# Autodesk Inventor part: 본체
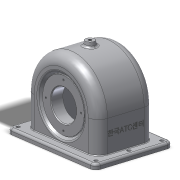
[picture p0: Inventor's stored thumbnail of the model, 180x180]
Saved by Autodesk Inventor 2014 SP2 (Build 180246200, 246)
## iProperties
Created: 2015-09
Part Number: 본체
Material: 알루미늄 6061
Document SubType Name: Modeling
Designer: 201-20
Density: 2.71 g/cm^3
Appearance: 알루미늄 - 평지
Mass: 723.189 g
Surface Area: 889.819 cm^2
Volume: 266.859 cm^3
Author: 201-20
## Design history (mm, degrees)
sketch "스케치6"
  geometry: L1 (-70, -40)-(70, -40); L2 (70, -40)-(70, -47); L3 (70, -47)-(-70, -47); L4 (-70, -47)-(-70, -40); 2 further points
  constraints: 8 end point, 2 parallel, 1 horizontal, 1 midpoint, 1 perpendicular, 1 vertical alignment
  dimensions: "d2" = 140 distance of L2.end L3.end; "d3" = 7 distance between parallel lines of L1 L3; "d4" = 47 distance from line of L3 point (0, 0)
extrude "돌출2" new body sketch "스케치6" stored distance "d5" = 104; taper "d6" = 0 deg
sketch "스케치10"
  geometry: L1 (70, -40)-(-70, -40) reference; L2 (-57, 0)-(57, 0); L3 (57, 0)-(57, -40); L4 (-57, -40)-(-57, 0); L5 (70, -47)-(-70, -47) reference; L6 (-51, 0)-(-51, -40); L7 (51, 0)-(51, -40); L8 (57, -40)-(51, -40); L9 (-51, -40)-(-57, -40); L10 (-51, -40)-(51, -40); A1 r 57 centre (0, 0) between (57, 0) and (-57, 0); A2 r 51 centre (0, 0) between (51, 0) and (-51, 0); 2 further points
  constraints: 16 end point, 5 perpendicular, 4 parallel, 4 point on circle, 3 midpoint, 2 centre point, 2 tangent, 1 coincident, 1 horizontal, 1 point on line, 1 vertical alignment
  dimensions: "d20" = 47 distance between parallel lines of L2 L5; "d21" = 6 radial gap between concentric circles of A1 A2; "d110" = 51 radius of A2
extrude "돌출3" join sketch "스케치10" stored distance "d17" = 77; taper "d18" = 0 deg
extrude "돌출4" cut sketch "스케치10" stored distance "d22" = 67; taper "d23" = 0 deg
sketch "스케치14"
  geometry: L1 (19, -18.5)-(121, -18.5); L2 (121, -18.5)-(121, -85.5); L3 (121, -85.5)-(19, -85.5); L4 (19, -85.5)-(19, -18.5); 3 further points
  constraints: 8 end point, 2 midpoint, 2 parallel, 1 horizontal, 1 horizontal alignment, 1 perpendicular, 1 vertical alignment
  dimensions: "d24" = 67 distance of L1.end L2.end; "d25" = 102 distance of L1.start L1.end
extrude "돌출5" cut sketch "스케치14" distance "d26" = 20; taper "d27" = 0 deg
fillet "모깎기1" dims "d28" = 14
fillet "모깎기3" dims "d34" = 9
sketch "스케치15"
  geometry: L1 (57, 38.5)-(0, 38.5) reference; L2 (51, 33.5)-(0, 33.5) reference; L3 (39.747, 33.5)-(28, 19.5); L4 (28, 19.5)-(20, 19.5); L5 (20, 19.5)-(20, 35.5); L6 (33, 33.237)-(37.416, 38.5); L7 (33, 33.237)-(33, 35.5); L8 (33, 35.5)-(20, 35.5); L9 (37.416, 38.5)-(39.747, 33.5); L10 (37.416, 38.5)-(20, 38.5); L11 (20, 38.5)-(20, 35.5); L12 (0, -72.8)-(0, 72.8) reference; 1 further point
  constraints: 18 end point, 3 parallel, 3 perpendicular, 3 point on line
  dimensions: "d30" = 28 horizontal distance of L3.end point (0, 0); "d31" = 3 distance between parallel lines of L8 L1; "d32" = 16 distance of L4.end L5.end; "d33" = 50 deg angle of L4 L3; "d35" = 33 distance from line of L7 point (0, 0); "d37" = 5 distance between parallel lines of L3 L6; "d38" = 20 distance from line of L5 point (0, 0)
revolve "회전1" stored, may be unused: angle "d39" = 90 deg
revolve "회전2" stored, may be unused: angle "d40" = 90 deg
sketch "스케치17"
  geometry: C1 r 31 at (0, 0); C2 r 20 at (0, 0); 1 further point
  constraints: 2 centre point, 2 coincident
  dimensions: "d41" = 62 diameter of C1; "d42" = 40 diameter of C2
extrude "돌출6" join sketch "스케치17" distance "d43" = 10; taper "d44" = 0 deg
sketch "스케치18"
  geometry: C1 r 20 at (0, 0) reference; 1 further point
extrude "돌출7" cut sketch "스케치18" distance "d45" = 87; taper "d46" = 0 deg
node "작업 평면2"
sketch "스케치20"
  geometry: C1 r 6 at (70, -52); 1 further point
  constraints: 1 centre point, 1 coincident
  dimensions: "d48" = 12 diameter of C1
extrude "돌출8" join sketch "스케치20" stored distance "d49" = 7; taper "d50" = 10 deg
hole "구멍1" diameter "d53" = 4.459; stored, may be unused: countersink angle "d57" = 90 deg, drill point angle "d59" = 0 deg; dims "d54" = 30, "d55" = 4, "d56" = 2, "d58" = 30, "d60" = 10, "d61" = 10
fillet "모깎기4" dims "d62" = 7
sketch "스케치21"
  geometry: 2 further points
  dimensions: "d63" = 62 horizontal distance of point (1, 8) point (63, 52); "d64" = 44 vertical distance of point (1, 8) point (63, 52)
hole "구멍2" sketch "스케치21" at (1, 8) diameter "d65" = 5; stored, may be unused: countersink angle "d69" = 90 deg, drill point angle "d71" = 0 deg; dims "d66" = 10, "d67" = 4, "d68" = 2, "d70" = 10
fillet "모깎기5" dims "d75" = 3, "d76" = 3, "d77" = 3, "d78" = 1
sketch "스케치22"
  geometry: 2 further points
  constraints: 1 vertical alignment
  dimensions: "d79" = 28 distance of point (0, 28) point (0, 0)
hole "구멍3" sketch "스케치22" at (0, 28) diameter "d80" = 2.459; stored, may be unused: countersink angle "d84" = 90 deg, drill point angle "d86" = 118 deg; dims "d81" = 7, "d82" = 4, "d83" = 2, "d85" = 9
chamfer "모따기1" distance "d90" = 1; stored, may be unused: second distance "d91" = 2, angle "d92" = 45 deg
fillet "모깎기6" dims "d93" = 0.5
sketch "스케치23"
  geometry: 2 further points
  constraints: 1 vertical alignment
  dimensions: "d94" = 24 distance of point (0, 24) point (0, 0)
hole "구멍4" sketch "스케치23" at (0, 24) diameter "d95" = 2.459; stored, may be unused: countersink angle "d99" = 90 deg, drill point angle "d101" = 118 deg; dims "d96" = 6, "d97" = 4, "d98" = 2, "d100" = 8
sketch "스케치24"
  geometry: L1 (-14, 0)-(-14, -39) reference; L2 (49, 0)-(0, 0) reference; L3 (-20.5, -47)-(69.5, -47) reference; 1 further point
  constraints: 1 other
  dimensions: "d108" = 38.5 distance from line of L1 point (24.5, -17); "d109" = 30 distance from line of point (24.5, -17) L3
feature "엠보싱1" sketch "스케치24" dims "d2" = 140, "d3" = 7, "d4" = 47, "d20" = 47, "d21" = 6, "d106" = 0.5, "d107" = 0, "d110" = 51
node "솔리드2"
pattern_linear "직사각형 패턴1" dims "d74" = 44
mirror "대칭1"
pattern_circular "원형 패턴1" dims angle "d88" = 360 deg
pattern_circular "원형 패턴2" dims angle "d103" = 360 deg
node "투영된 루프2"
